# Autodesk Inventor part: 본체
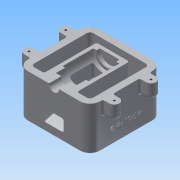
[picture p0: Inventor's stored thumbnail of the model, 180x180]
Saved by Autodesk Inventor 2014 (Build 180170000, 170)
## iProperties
Created: 2018-01
Part Number: 본체
Material: 알루미늄 6061
Document SubType Name: Modeling
Designer: Administrator
Density: 2.71 g/cm^3
Appearance: 알루미늄 - 평지
Mass: 999.826 g
Surface Area: 837.427 cm^2
Volume: 368.94 cm^3
Author: Administrator
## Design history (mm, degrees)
sketch "스케치2"
  geometry: L1 (40, -55)-(-40, -55); L2 (-55, -40)-(-55, 40); L3 (-40, 55)-(40, 55); L4 (55, 40)-(55, -40); L5 (55, -55)-(-55, 55); L6 (-55, -55)-(55, 55); A1 r 15 centre (-40, 40) between (-40, 55) and (-55, 40); A2 r 15 centre (40, 40) between (55, 40) and (40, 55); A3 r 15 centre (40, -40) between (40, -55) and (55, -40); A4 r 15 centre (-40, -40) between (-55, -40) and (-40, -55); 1 further point
  constraints: 12 end point, 8 point on circle, 8 point on line, 8 tangent, 4 centre point, 3 equal radius, 2 midpoint, 2 parallel, 1 horizontal, 1 perpendicular
  dimensions: "d0" = 110 distance of L5.end L6.end; "d1" = 110 distance of L6.start L5.end; "d2" = 15 radius of A1
extrude "돌출1" new body sketch "스케치2" stored distance "d3" = 65; taper "d4" = 0 deg
sketch "스케치3"
  geometry: L1 (40, 55)-(-40, 55) reference; L2 (-55, 40)-(-55, -40) reference; L3 (-40, -55)-(40, -55) reference; L4 (55, -40)-(55, 40) reference; L5 (40, -45)-(-40, -45); L6 (-45, -40)-(-45, 40); L7 (-40, 45)-(40, 45); L8 (45, 40)-(45, -40); A1 r 15 centre (-40, 40) between (-40, 55) and (-55, 40) reference; A2 r 15 centre (-40, -40) between (-55, -40) and (-40, -55) reference; A3 r 15 centre (40, -40) between (40, -55) and (55, -40) reference; A4 r 15 centre (40, 40) between (55, 40) and (40, 55) reference; A5 r 5 centre (-40, -40) between (-45, -40) and (-40, -45); A6 r 5 centre (-40, 40) between (-40, 45) and (-45, 40); A7 r 5 centre (40, 40) between (45, 40) and (40, 45); A8 r 5 centre (40, -40) between (40, -45) and (45, -40); 1 further point
  constraints: 8 end point, 8 point on circle, 4 centre point, 7 other
  dimensions: "d5" = 10 distance between parallel lines of L3 L5
extrude "돌출2" cut sketch "스케치3" distance "d6" = 65; taper "d7" = 0 deg
sketch "스케치4"
  geometry: L1 (32.5, 45)-(-32.5, 45) reference; L2 (-32.5, 45)-(-32.5, 55) reference; L3 (-32.5, 55)-(32.5, 55) reference; L4 (32.5, 55)-(32.5, 45) reference; L5 (-32.5, -45)-(32.5, -45) reference; L6 (32.5, -45)-(32.5, -55) reference; L7 (32.5, -55)-(-32.5, -55) reference; L8 (-32.5, -55)-(-32.5, -45) reference; L9 (-23.936, 45)-(-2.5, -35); L10 (-2.5, -35)-(32.5, -35); L11 (32.5, -35)-(32.5, 45); L12 (32.5, 45)-(-23.936, 45); L13 (-32.5, -40)-(-32.5, 40) reference; L14 (32.5, 40)-(32.5, -40) reference; 1 further point
  constraints: 8 end point, 3 perpendicular, 2 collinear
  dimensions: "d8" = 30 distance from line of L13 L9.end; "d9" = 20 distance between parallel lines of L7 L10; "d10" = 105 deg angle of L1 L9
extrude "돌출3" join sketch "스케치4" stored distance "d11" = 50; taper "d12" = 0 deg
sketch "스케치5"
  geometry: L1 (32.5, -35)-(-2.5, -35) reference; L2 (-2.5, -35)-(-23.936, 45) reference; L3 (-23.936, 45)-(-32.5, 45) reference; L4 (-32.5, 45)-(-32.5, 55) reference; L5 (-32.5, 55)-(32.5, 55) reference; L6 (32.5, 55)-(32.5, -35) reference; L7 (-32.5, -45)-(32.5, -45) reference; L8 (32.5, -45)-(32.5, -55) reference; L9 (32.5, -55)-(-32.5, -55) reference; L10 (-32.5, -55)-(-32.5, -45) reference; L11 (32.5, 55)-(-32.5, 55) reference; L12 (-32.5, 40)-(32.5, 40) reference; L13 (25, 55)-(25, 37); L14 (24, 36)-(17.5, 36); L15 (16.5, 35)-(16.5, 22); L16 (16.5, 22)-(13.5, 22); L17 (12.5, 21)-(12.5, -24); L18 (13.5, -25)-(17.5, -25); L19 (17.5, -25)-(17.5, -29); L20 (18.5, -30)-(32.5, -30); L21 (25, 55)-(32.5, 55); L22 (32.5, 55)-(32.5, -30); L23 (25, 37)-(24, 36); A1 r 1 centre (17.5, 35) between (17.5, 36) and (16.5, 35); A2 r 1 centre (13.5, 21) between (13.5, 22) and (12.5, 21); A3 r 1 centre (13.5, -24) between (12.5, -24) and (13.5, -25); A4 r 1 centre (18.5, -29) between (17.5, -29) and (18.5, -30); 2 further points
  constraints: 22 end point, 8 point on circle, 8 tangent, 6 parallel, 4 centre point, 4 point on line, 3 equal radius, 2 collinear, 2 perpendicular
  dimensions: "d13" = 7.5 distance between parallel lines of L22 L13; "d14" = 16 distance between parallel lines of L6 L15; "d15" = 20 distance between parallel lines of L6 L17; "d16" = 15 distance between parallel lines of L6 L19; "d17" = 19 distance between parallel lines of L14 L5; "d18" = 14 distance between parallel lines of L16 L14; "d19" = 47 distance between parallel lines of L18 L16; "d20" = 5 distance between parallel lines of L20 L18; "d21" = 1 radius of A1; "d68" = 1 distance of L13.end point (25, 36); "d69" = 1 distance of L14.start point (25, 36) (= d68)
revolve "회전1" sketch "스케치5" stored, may be unused: angle "d22" = 90 deg
sketch "스케치6"
  geometry: L1 (25, 55)-(25, 37) reference; L2 (24, 36)-(17.5, 36) reference; L3 (16.5, 35)-(16.5, 22) reference; L4 (16.5, 22)-(13.5, 22) reference; L5 (12.5, 21)-(12.5, -24) reference; L6 (13.5, -25)-(17.5, -25) reference; L7 (17.5, -25)-(17.5, -29) reference; L8 (18.5, -30)-(32.5, -30) reference; L9 (32.5, -30)-(32.5, -35) reference; L10 (32.5, -35)-(-2.5, -35) reference; L11 (-2.5, -35)-(-23.936, 45) reference; L12 (-23.936, 45)-(-32.5, 45) reference; L13 (-32.5, 45)-(-32.5, 55) reference; L14 (-32.5, 55)-(25, 55) reference; L15 (32.5, -45)-(32.5, -55) reference; L16 (32.5, -55)-(-32.5, -55) reference; L17 (-32.5, -55)-(-32.5, -45) reference; L18 (-32.5, -45)-(32.5, -45) reference; L19 (-21.439, 55)-(-1.939, -17.776); L20 (0.959, -20)-(22.387, -20); L21 (9.045, 17)-(22.387, 17); L22 (-3.439, 55)-(6.147, 19.224); L23 (-21.439, 55)-(-3.439, 55); L24 (25, 55)-(25, 37) reference; L25 (24, 36)-(17.5, 36) reference; L26 (16.5, 35)-(16.5, 22) reference; L27 (16.5, 22)-(13.5, 22) reference; L28 (12.5, 21)-(12.5, -24) reference; L29 (13.5, -25)-(17.5, -25) reference; L30 (17.5, -25)-(17.5, -29) reference; L31 (18.5, -30)-(32.5, -30) reference; L32 (32.5, -30)-(32.5, -35) reference; L33 (32.5, -35)-(-2.5, -35) reference; L34 (-2.5, -35)-(-23.936, 45) reference; L35 (-23.936, 45)-(-32.5, 45) reference; L36 (-32.5, 45)-(-32.5, 55) reference; L37 (-32.5, 55)-(25, 55) reference; L38 (32.5, -45)-(32.5, -55) reference; L39 (32.5, -55)-(-32.5, -55) reference; L40 (-32.5, -55)-(-32.5, -45) reference; L41 (-32.5, -45)-(32.5, -45) reference; L42 (32.5, 21)-(32.5, -24) reference; L43 (22.387, 17)-(22.387, -20); L44 (25, 37)-(24, 36) reference; L45 (25, 37)-(24, 36) reference; A1 r 1 centre (17.5, 35) between (17.5, 36) and (16.5, 35) reference; A2 r 1 centre (13.5, 21) between (13.5, 22) and (12.5, 21) reference; A3 r 1 centre (13.5, -24) between (12.5, -24) and (13.5, -25) reference; A4 r 1 centre (18.5, -29) between (17.5, -29) and (18.5, -30) reference; A5 r 3 centre (9.045, 20) between (6.147, 19.224) and (9.045, 17); A6 r 3 centre (0.959, -17) between (-1.939, -17.776) and (0.959, -20); A7 r 1 centre (17.5, 35) between (17.5, 36) and (16.5, 35) reference; A8 r 1 centre (13.5, 21) between (13.5, 22) and (12.5, 21) reference; A9 r 1 centre (13.5, -24) between (12.5, -24) and (13.5, -25) reference; A10 r 1 centre (18.5, -29) between (17.5, -29) and (18.5, -30) reference; 2 further points
  constraints: 12 end point, 4 point on circle, 4 point on line, 4 tangent, 2 centre point, 2 parallel, 1 collinear, 1 equal radius, 1 perpendicular
  dimensions: "d23" = 5 distance between parallel lines of L11 L19; "d24" = 18 distance of L22.start L19.start; "d26" = 75 deg angle of L14 L22; "d27" = 90 deg angle of L5 L21; "d28" = 3 radius of A5; "d55" = 37 distance of L21.end L20.end; "d56" = 9.88673 distance between parallel lines of L5 L43; "d57" = 13.34172 distance of L21.start L21.end
extrude "돌출4" cut sketch "스케치6" stored distance "d29" = 30; taper "d30" = 0 deg
sketch "스케치8"
  geometry: L1 (7.5, -55)-(40, -55) reference; L2 (55, -40)-(55, 40) reference; L3 (45, 40)-(45, -40) reference; L4 (-40, 45)-(40, 45) reference; L5 (65, -20.5)-(45, -20.5); L6 (65.588, -35.5)-(45, -35.5); L7 (40, 45)-(-40, 45) reference; L8 (-45, 40)-(-45, -40) reference; L9 (-40, -45)-(-25, -45) reference; L10 (-25, -45)-(-25, 35) reference; L11 (-25, 35)-(25, 35) reference; L12 (25, 35)-(25, -45) reference; L13 (25, -45)-(40, -45) reference; L14 (45, -40)-(45, 40) reference; L15 (-55, -40)-(-55, 40) reference; L16 (-40, 55)-(40, 55) reference; L17 (55, 40)-(55, -40) reference; L18 (40, -55)-(7.5, -55) reference; L19 (7.5, -55)-(7.5, -37) reference; L20 (8.5, -36)-(15, -36) reference; L21 (16, -35)-(16, -22) reference; L22 (16, -22)-(19, -22) reference; L23 (20, -21)-(20, 24) reference; L24 (19, 25)-(15, 25) reference; L25 (15, 25)-(15, 29) reference; L26 (-15, 29)-(-15, 25) reference; L27 (-15, 25)-(-19, 25) reference; L28 (-20, 24)-(-20, -21) reference; L29 (-19, -22)-(-16, -22) reference; L30 (-16, -22)-(-16, -35) reference; L31 (-15, -36)-(-8.5, -36) reference; L32 (-7.5, -37)-(-7.5, -55) reference; L33 (-7.5, -55)-(-40, -55) reference; L34 (-7.5, -55)-(-7.5, -37) reference; L35 (-8.5, -36)-(-15, -36) reference; L36 (-16, -35)-(-16, -22) reference; L37 (-16, -22)-(-19, -22) reference; L38 (-20, -21)-(-20, 24) reference; L39 (-19, 25)-(-15, 25) reference; L40 (-15, 25)-(-15, 29) reference; L41 (15, 29)-(15, 25) reference; L42 (15, 25)-(19, 25) reference; L43 (20, 24)-(20, -21) reference; L44 (19, -22)-(16, -22) reference; L45 (16, -22)-(16, -35) reference; L46 (15, -36)-(8.5, -36) reference; L47 (7.5, -37)-(7.5, -55) reference; L48 (7.5, -55)-(40, -55) reference; L49 (55, -40)-(55, 40) reference; L50 (40, 55)-(-40, 55) reference; L51 (-55, 40)-(-55, -40) reference; L52 (-40, -55)-(-7.5, -55) reference; L53 (45, 40)-(45, -40) reference; L54 (40, -45)-(25, -45) reference; L55 (25, 35)-(25, -45) reference; L56 (-25, 35)-(25, 35) reference; L57 (-25, -45)-(-25, 35) reference; L58 (-25, -45)-(-40, -45) reference; L59 (-45, -40)-(-45, 40) reference; L60 (-40, 45)-(40, 45) reference; L61 (14, 30)-(-14, 30) reference; L62 (-14, 30)-(14, 30) reference; L63 (7.5, -37)-(8.5, -36) reference; L64 (-8.5, -36)-(-7.5, -37) reference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; A1 r 7.5 centre (65, -28) between (65, -35.5) and (65, -20.5); A2 r 5 centre (40, 40) between (45, 40) and (40, 45) reference; A3 r 5 centre (-40, 40) between (-40, 45) and (-45, 40) reference; A4 r 5 centre (-40, -40) between (-45, -40) and (-40, -45) reference; A5 r 5 centre (40, -40) between (40, -45) and (45, -40) reference; A6 r 15 centre (-40, -40) between (-55, -40) and (-40, -55) reference; A7 r 15 centre (-40, 40) between (-40, 55) and (-55, 40) reference; A8 r 15 centre (40, 40) between (55, 40) and (40, 55) reference; A9 r 15 centre (40, -40) between (40, -55) and (55, -40) reference; A10 r 1 centre (15, -35) between (15, -36) and (16, -35) reference; A11 r 1 centre (19, -21) between (19, -22) and (20, -21) reference; A12 r 1 centre (19, 24) between (20, 24) and (19, 25) reference; A13 r 1 centre (14, 29) between (15, 29) and (14, 30) reference; A14 r 1 centre (-14, 29) between (-14, 30) and (-15, 29) reference; A15 r 1 centre (-19, 24) between (-19, 25) and (-20, 24) reference; A16 r 1 centre (-19, -21) between (-20, -21) and (-19, -22) reference; A17 r 1 centre (-15, -35) between (-16, -35) and (-15, -36) reference; A18 r 1 centre (-15, -35) between (-16, -35) and (-15, -36) reference; A19 r 1 centre (-19, -21) between (-20, -21) and (-19, -22) reference; A20 r 1 centre (-19, 24) between (-19, 25) and (-20, 24) reference; A21 r 1 centre (-14, 29) between (-14, 30) and (-15, 29) reference; A22 r 1 centre (14, 29) between (15, 29) and (14, 30) reference; A23 r 1 centre (19, 24) between (20, 24) and (19, 25) reference; A24 r 1 centre (19, -21) between (19, -22) and (20, -21) reference; A25 r 1 centre (15, -35) between (15, -36) and (16, -35) reference; A26 r 15 centre (40, -40) between (40, -55) and (55, -40) reference; A27 r 15 centre (40, 40) between (55, 40) and (40, 55) reference; A28 r 15 centre (-40, 40) between (-40, 55) and (-55, 40) reference; A29 r 15 centre (-40, -40) between (-55, -40) and (-40, -55) reference; A30 r 5 centre (40, 40) between (45, 40) and (40, 45) reference; A31 r 5 centre (40, -40) between (40, -45) and (45, -40) reference; A32 r 5 centre (-40, -40) between (-45, -40) and (-40, -45) reference; A33 r 5 centre (-40, 40) between (-40, 45) and (-45, 40) reference; 4 further points
  constraints: 4 end point, 3 point on line, 2 parallel, 2 point on circle, 2 tangent, 1 centre point, 1 coincident
  dimensions: "d35" = 15 diameter of A1; "d36" = 27 distance from line of A1.centre L1; "d37" = 10 distance from line of L2 A1.centre
  node "절단 모서리 투영4"
  node "투영된 루프1"
extrude "돌출5" join sketch "스케치8" distance "d38" = 20; taper "d39" = 0 deg
hole "구멍1" sketch "스케치8" diameter "d40" = 3.242; stored, may be unused: countersink angle "d44" = 90 deg, drill point angle "d46" = 118 deg; dims "d41" = 9, "d42" = 4, "d43" = 2, "d45" = 11
fillet "모깎기3" dims "d49" = 3
fillet "모깎기4" dims "d58" = 3
fillet "모깎기5" dims "d59" = 3
fillet "모깎기6" dims "d60" = 3
sketch "스케치9"
  geometry: L1 (80, 0)-(0, 0) reference; L2 (-15, 0)-(-15, 65) reference; 2 further points
  constraints: 1 other
  dimensions: "d61" = 20 distance from line of L1 point (40, 20); "d62" = 55 distance from line of L2 point (40, 20)
feature "엠보싱1" sketch "스케치9" dims "d0" = 110, "d1" = 110, "d2" = 15, "d63" = 0.5, "d64" = 0
fillet "모깎기7" dims "d65" = 3
fillet "모깎기8" dims "d66" = 3
fillet "모깎기9" dims "d67" = 1
node "솔리드1"
mirror "대칭1"
mirror "대칭2"
node "절단 모서리 투영1"
node "절단 모서리 투영2"
node "절단 모서리 투영3"
node "절단 모서리 투영5"
